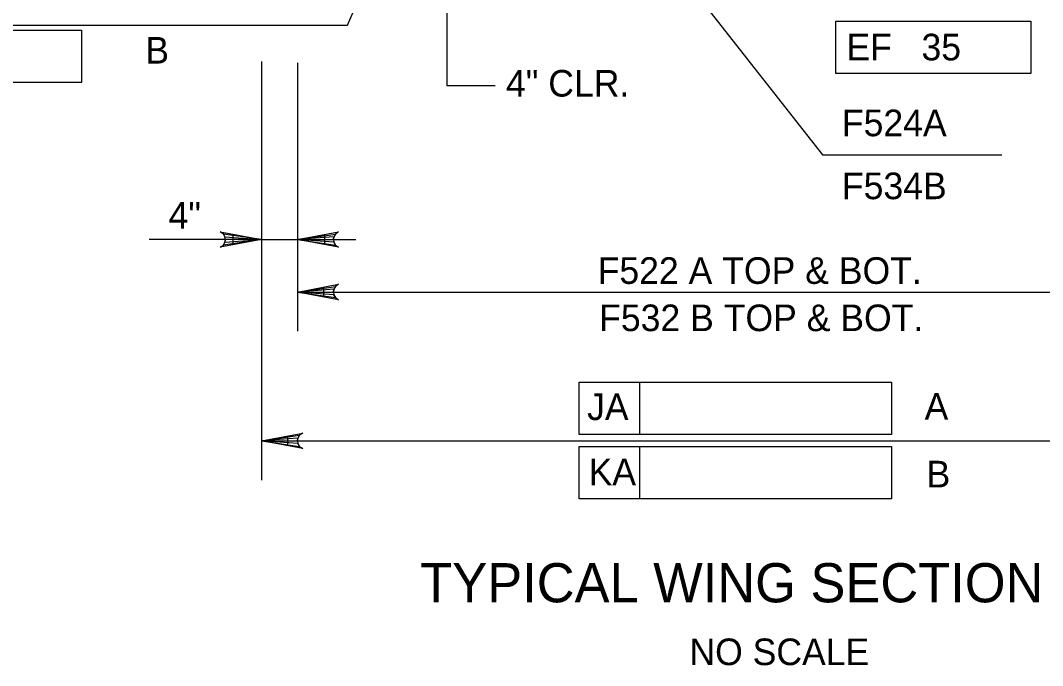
# Model space of a CAD drawing. Extents: x 638255 to 640306, y 296059 to 298435.
# Drawn here: x 639907 to 640022.3, y 297516.2 to 297588.9 of the extents above; entities that cross this region are included whole.
import ezdxf

# ---------------------------------------------------------------- set-up
doc = ezdxf.new("R2010")
doc.units = 0
for name, color, linetype in [('Level 3', 7, 'Continuous'), ('Level 4', 7, 'Continuous'), ('Level 6', 7, 'Continuous')]:
    doc.layers.add(name, color=color, linetype=linetype)

msp = doc.modelspace()

# ---------------------------------------------------------------- linework, layer by layer
at = {"layer": 'Level 3'}
msp.add_line((639943.86, 297588.38), (639949.14, 297600.62), dxfattribs=at)
at = {"layer": 'Level 4'}
for p, q in [((639967.91, 297611.42), (639997.43, 297573.76)), ((639955.06, 297594.2), (639955.06, 297581.53)), ((639892, 297588.38), (639943.86, 297588.38)), ((639998.95, 297588.82), (640020.95, 297588.82)), ((639998.95, 297582.93), (639998.95, 297588.82)), ((640020.95, 297588.82), (640020.95, 297582.93)), ((639894.96, 297587.8), (639913.87, 297587.8)), ((639913.87, 297587.8), (639913.87, 297581.9)), ((639934.15, 297584.3), (639934.15, 297537.09)), ((639938.21, 297584.14), (639938.21, 297553.86)), ((640020.95, 297582.93), (639998.95, 297582.93)), ((639913.87, 297581.9), (639894.96, 297581.9)), ((639997.43, 297573.76), (640017.66, 297573.76)), ((639934.15, 297564.21), (639921.49, 297564.21)), ((639934.15, 297564.21), (639944.79, 297564.21)), ((639938.21, 297558.28), (640044.15, 297558.28)), ((639970, 297548.13), (640005.23, 297548.13)), ((639970, 297542.24), (639970, 297548.13)), ((639976.83, 297542.24), (639976.83, 297548.13)), ((640005.23, 297548.13), (640005.23, 297542.24)), ((640005.23, 297542.24), (639970, 297542.24)), ((639934.15, 297541.51), (640048.21, 297541.51)), ((639970, 297540.86), (640005.23, 297540.86)), ((639970, 297534.96), (639970, 297540.86)), ((639976.83, 297534.96), (639976.83, 297540.86)), ((640005.23, 297540.86), (640005.23, 297534.96)), ((640005.23, 297534.96), (639970, 297534.96))]:
    msp.add_line(p, q, dxfattribs=at)
for points in [[(639934.15, 297564.21), (639929.5, 297563.34), (639929.86, 297563.58), (639930.04, 297563.9), (639930.1, 297564.21), (639930.04, 297564.52), (639929.86, 297564.83), (639929.5, 297565.08), (639934.15, 297564.21), (639929.86, 297564.83), (639930.04, 297564.52), (639934.15, 297564.21), (639930.1, 297564.21), (639930.04, 297563.9), (639934.15, 297564.21), (639929.86, 297563.58)], [(639938.21, 297564.21), (639942.86, 297565.08), (639942.51, 297564.83), (639942.32, 297564.52), (639942.27, 297564.21), (639942.32, 297563.9), (639942.51, 297563.58), (639942.86, 297563.34), (639938.21, 297564.21), (639942.51, 297563.58), (639942.32, 297563.9), (639938.21, 297564.21), (639942.27, 297564.21), (639942.32, 297564.52), (639938.21, 297564.21), (639942.51, 297564.83)], [(639938.21, 297558.28), (639942.86, 297559.16), (639942.51, 297558.91), (639942.32, 297558.6), (639942.27, 297558.28), (639942.32, 297557.97), (639942.51, 297557.66), (639942.86, 297557.41), (639938.21, 297558.28), (639942.51, 297557.66), (639942.32, 297557.97), (639938.21, 297558.28), (639942.27, 297558.28), (639942.32, 297558.6), (639938.21, 297558.28), (639942.51, 297558.91)], [(639934.15, 297541.51), (639938.81, 297542.39), (639938.45, 297542.14), (639938.26, 297541.83), (639938.21, 297541.51), (639938.26, 297541.2), (639938.45, 297540.89), (639938.81, 297540.64), (639934.15, 297541.51), (639938.45, 297540.89), (639938.26, 297541.2), (639934.15, 297541.51), (639938.21, 297541.51), (639938.26, 297541.83), (639934.15, 297541.51), (639938.45, 297542.14)]]:
    msp.add_lwpolyline(points, dxfattribs=at)
for points in [[(639930.93, 297564.7), (639930.93, 297563.72), (639933.88, 297564.21)], [(639941.29, 297563.72), (639941.29, 297564.7), (639938.35, 297564.21)], [(639941.16, 297558.78), (639941.16, 297557.79), (639938.21, 297558.28)], [(639937.1, 297542.01), (639937.1, 297541.02), (639934.15, 297541.51)]]:
    msp.add_lwpolyline(points, close=True, dxfattribs=at)
at = {"layer": 'Level 6'}
msp.add_line((639960.53, 297581.53), (639955.06, 297581.53), dxfattribs=at)

# ---------------------------------------------------------------- texts
at = {"layer": 'Level 3'}
for s, p in [('4" CLR.', (639961.74, 297580.33)), ('4"', (639923.68, 297565.45))]:
    msp.add_text(s, height=3, dxfattribs=at).set_placement(p)
at = {"layer": 'Level 4'}
for s, height, p in [('B', 3, (639921.06, 297584.05)), ('EF   35', 3, (640000.14, 297584.41)), ('F524A', 3, (639999.63, 297575.86)), ('F534B', 3, (639999.63, 297568.76)), ('F522 A TOP & BOT.', 3.0001, (639972.08, 297559.21)), ('F532 B TOP & BOT.', 3.0001, (639972.25, 297553.88)), ('JA', 3, (639970.89, 297543.85)), ('A', 3, (640008.96, 297543.89)), ('KA', 3, (639971.06, 297536.51)), ('B', 3, (640009.18, 297536.26)), ('TYPICAL WING SECTION', 4.4207, (639952.07, 297523.3)), ('NO SCALE', 3, (639982.43, 297516.22))]:
    msp.add_text(s, height=height, dxfattribs=at).set_placement(p)

doc.saveas('drawing.dxf')
